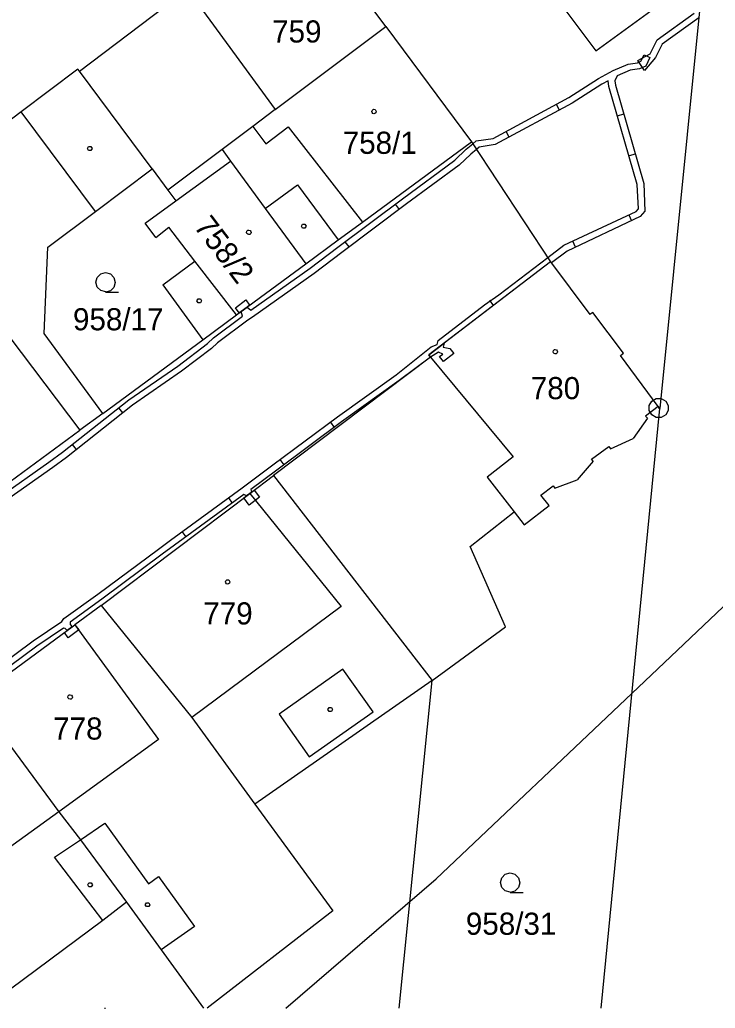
# Model space of a CAD drawing. Extents: x -777309 to -774195, y -1144706 to -1143600.
# Drawn here: x -775185.7 to -775132.3, y -1144700 to -1144624.1 of the extents above; entities that cross this region are included whole.
import ezdxf

# ---------------------------------------------------------------- set-up
doc = ezdxf.new("R2010")
doc.units = 0
for name, color, linetype in [('1', 7, 'Continuous'), ('11', 7, 'Continuous'), ('12', 7, 'Continuous'), ('13', 7, 'Continuous'), ('2', 7, 'Continuous'), ('3', 7, 'Continuous'), ('4', 7, 'Continuous'), ('5', 7, 'Continuous'), ('8', 7, 'Continuous')]:
    doc.layers.add(name, color=color, linetype=linetype)

msp = doc.modelspace()

# ---------------------------------------------------------------- linework, layer by layer
at = {"layer": '1'}
for p, q in [((-775157.61, -1144624.62), (-775164.34, -1144615.55)), ((-775141.48, -1144626.47), (-775133.23, -1144620.45)), ((-775133.23, -1144620.45), (-775136.58, -1144653.95)), ((-775181.15, -1144628.05), (-775172.84, -1144621.74)), ((-775144.69, -1144622.2), (-775141.48, -1144626.47)), ((-775166.11, -1144630.99), (-775157.61, -1144624.62)), ((-775157.61, -1144624.62), (-775151.04, -1144633.47)), ((-775181.27, -1144627.89), (-775185.64, -1144631.15)), ((-775181.15, -1144628.05), (-775181.27, -1144627.89)), ((-775175.57, -1144635.55), (-775181.15, -1144628.05)), ((-775185.64, -1144631.15), (-775189.64, -1144634.21)), ((-775166.11, -1144630.99), (-775167.84, -1144632.28)), ((-775167.84, -1144632.28), (-775170.2, -1144634.05)), ((-775159.42, -1144639.64), (-775151.04, -1144633.47)), ((-775151.04, -1144633.47), (-775144.97, -1144642.68)), ((-775170.2, -1144634.05), (-775174.36, -1144637.17)), ((-775170.2, -1144634.05), (-775169.55, -1144634.94)), ((-775169.55, -1144634.94), (-775166.89, -1144638.59)), ((-775179.93, -1144638.81), (-775175.57, -1144635.55)), ((-775175.57, -1144635.55), (-775174.36, -1144637.17)), ((-775174.36, -1144637.17), (-775173.74, -1144638)), ((-775176.1, -1144639.72), (-775173.74, -1144638)), ((-775183.59, -1144641.55), (-775179.93, -1144638.81)), ((-775166.89, -1144638.59), (-775163.77, -1144642.84)), ((-775175.28, -1144640.81), (-775176.1, -1144639.72)), ((-775161.27, -1144641), (-775159.42, -1144639.64)), ((-775175.28, -1144640.81), (-775174.29, -1144640.02)), ((-775172.28, -1144642.63), (-775174.29, -1144640.02)), ((-775163.77, -1144642.84), (-775161.27, -1144641)), ((-775183.87, -1144648.18), (-775183.59, -1144641.55)), ((-775174.76, -1144644.46), (-775172.28, -1144642.63)), ((-775169.09, -1144646.76), (-775163.77, -1144642.84)), ((-775144.97, -1144642.68), (-775154.31, -1144649.83)), ((-775144.97, -1144642.68), (-775141.94, -1144646.72)), ((-775174.76, -1144644.46), (-775171.67, -1144648.66)), ((-775141.72, -1144646.56), (-775141.94, -1144646.72)), ((-775139.37, -1144649.7), (-775141.72, -1144646.56)), ((-775187.72, -1144646.9), (-775181.13, -1144655.62)), ((-775171.67, -1144648.66), (-775169.09, -1144646.76)), ((-775179.36, -1144654.32), (-775183.87, -1144648.18)), ((-775179.36, -1144654.32), (-775171.67, -1144648.66)), ((-775154.19, -1144649.99), (-775166.24, -1144659.08)), ((-775154.31, -1144649.83), (-775154.19, -1144649.99)), ((-775139.6, -1144649.87), (-775139.37, -1144649.7)), ((-775136.71, -1144653.79), (-775139.6, -1144649.87)), ((-775141.074, -1144700), (-775136.58, -1144653.95)), ((-775136.71, -1144653.79), (-775137.66, -1144654.53)), ((-775136.71, -1144653.79), (-775136.58, -1144653.95)), ((-775179.36, -1144654.32), (-775181.13, -1144655.62)), ((-775137.53, -1144654.68), (-775138.62, -1144656.25)), ((-775137.66, -1144654.53), (-775137.53, -1144654.68)), ((-775190.02, -1144662.15), (-775181.13, -1144655.62)), ((-775140.36, -1144657.04), (-775138.62, -1144656.25)), ((-775141.81, -1144657.83), (-775140.48, -1144656.87)), ((-775140.48, -1144656.87), (-775140.36, -1144657.04)), ((-775141.69, -1144658), (-775142.92, -1144659.43)), ((-775141.69, -1144658), (-775141.81, -1144657.83)), ((-775168.07, -1144660.46), (-775166.24, -1144659.08)), ((-775166.24, -1144659.08), (-775154.07, -1144674.84)), ((-775144.63, -1144660.05), (-775142.92, -1144659.43)), ((-775145.7, -1144660.59), (-775144.76, -1144659.88)), ((-775144.76, -1144659.88), (-775144.63, -1144660.05)), ((-775179.48, -1144669.07), (-775168.07, -1144660.46)), ((-775145.08, -1144661.39), (-775145.7, -1144660.59)), ((-775146.99, -1144662.87), (-775145.08, -1144661.39)), ((-775151.13, -1144664.54), (-775147.76, -1144661.89)), ((-775147.76, -1144661.89), (-775146.99, -1144662.87)), ((-775148.42, -1144670.72), (-775151.13, -1144664.54)), ((-775179.48, -1144669.07), (-775181.5, -1144670.55)), ((-775179.48, -1144669.07), (-775172.51, -1144677.68)), ((-775189.17, -1144676.2), (-775181.5, -1144670.55)), ((-775154.07, -1144674.84), (-775148.42, -1144670.72)), ((-775154.07, -1144674.84), (-775167.67, -1144684.33)), ((-775156.607, -1144700), (-775154.07, -1144674.84)), ((-775189.17, -1144676.2), (-775182.75, -1144684.92)), ((-775172.51, -1144677.68), (-775167.67, -1144684.33)), ((-775167.67, -1144684.33), (-775161.68, -1144692.51)), ((-775182.75, -1144684.92), (-775181.07, -1144687.07)), ((-775181.07, -1144687.07), (-775177.55, -1144691.86)), ((-775177.55, -1144691.86), (-775179.35, -1144693.26)), ((-775177.55, -1144691.86), (-775174.87, -1144695.51)), ((-775161.68, -1144692.51), (-775171.339, -1144700)), ((-775179.35, -1144693.26), (-775187.68, -1144699.45)), ((-775174.87, -1144695.51), (-775171.621, -1144700))]:
    msp.add_line(p, q, dxfattribs=at)
at = {"layer": '11'}
msp.add_lwpolyline([(-775165.303, -1144700), (-775153.75, -1144690.06), (-775138.71, -1144675.82), (-775130.21, -1144667.77)], dxfattribs=at)
at = {"layer": '12'}
for p, q in [((-775157.61, -1144624.62), (-775164.34, -1144615.55)), ((-775172.84, -1144621.74), (-775166.11, -1144630.99)), ((-775166.11, -1144630.99), (-775157.61, -1144624.62)), ((-775166.11, -1144630.99), (-775157.61, -1144624.62)), ((-775157.61, -1144624.62), (-775151.04, -1144633.47)), ((-775166.11, -1144630.99), (-775167.84, -1144632.28)), ((-775167.84, -1144632.28), (-775166.84, -1144633.61)), ((-775166.84, -1144633.61), (-775165.11, -1144632.32)), ((-775165.11, -1144632.32), (-775159.42, -1144639.64)), ((-775159.42, -1144639.64), (-775151.04, -1144633.47)), ((-775173.74, -1144638), (-775169.55, -1144634.94)), ((-775169.55, -1144634.94), (-775166.89, -1144638.59)), ((-775176.1, -1144639.72), (-775173.74, -1144638)), ((-775166.89, -1144638.59), (-775163.77, -1144642.84)), ((-775175.28, -1144640.81), (-775176.1, -1144639.72)), ((-775175.28, -1144640.81), (-775174.29, -1144640.02)), ((-775172.28, -1144642.63), (-775174.29, -1144640.02)), ((-775169.09, -1144646.76), (-775172.28, -1144642.63)), ((-775169.09, -1144646.76), (-775163.77, -1144642.84)), ((-775144.97, -1144642.68), (-775154.31, -1144649.83)), ((-775144.97, -1144642.68), (-775141.94, -1144646.72)), ((-775141.72, -1144646.56), (-775141.94, -1144646.72)), ((-775139.37, -1144649.7), (-775141.72, -1144646.56)), ((-775154.31, -1144649.83), (-775154.19, -1144649.99)), ((-775154.19, -1144649.99), (-775147.85, -1144657.66)), ((-775139.6, -1144649.87), (-775139.37, -1144649.7)), ((-775136.71, -1144653.79), (-775139.6, -1144649.87)), ((-775136.71, -1144653.79), (-775137.66, -1144654.53)), ((-775137.53, -1144654.68), (-775138.62, -1144656.25)), ((-775137.66, -1144654.53), (-775137.53, -1144654.68)), ((-775140.36, -1144657.04), (-775138.62, -1144656.25)), ((-775141.81, -1144657.83), (-775140.48, -1144656.87)), ((-775140.48, -1144656.87), (-775140.36, -1144657.04)), ((-775147.85, -1144657.66), (-775149.84, -1144659.21)), ((-775141.69, -1144658), (-775142.92, -1144659.43)), ((-775141.69, -1144658), (-775141.81, -1144657.83)), ((-775149.84, -1144659.21), (-775147.76, -1144661.89)), ((-775144.63, -1144660.05), (-775142.92, -1144659.43)), ((-775145.7, -1144660.59), (-775144.76, -1144659.88)), ((-775144.76, -1144659.88), (-775144.63, -1144660.05)), ((-775179.48, -1144669.07), (-775168.07, -1144660.46)), ((-775168.07, -1144660.46), (-775161.04, -1144669.16)), ((-775145.08, -1144661.39), (-775145.7, -1144660.59)), ((-775146.99, -1144662.87), (-775145.08, -1144661.39)), ((-775147.76, -1144661.89), (-775146.99, -1144662.87)), ((-775179.48, -1144669.07), (-775172.51, -1144677.68)), ((-775161.04, -1144669.16), (-775172.51, -1144677.68)), ((-775189.17, -1144676.2), (-775181.5, -1144670.55)), ((-775181.5, -1144670.55), (-775175.07, -1144679.37)), ((-775189.17, -1144676.2), (-775182.75, -1144684.92)), ((-775189.17, -1144676.2), (-775182.75, -1144684.92)), ((-775175.07, -1144679.37), (-775182.75, -1144684.92)), ((-775182.75, -1144684.92), (-775190.37, -1144690.43))]:
    msp.add_line(p, q, dxfattribs=at)
at = {"layer": '13'}
for p, q in [((-775136.78, -1144625.63), (-775133.93, -1144623.59)), ((-775133.58, -1144623.95), (-775136.38, -1144625.97)), ((-775137.32, -1144626.7), (-775136.78, -1144625.63)), ((-775136.38, -1144625.97), (-775136.9, -1144626.98)), ((-775138.27, -1144627.21), (-775137.32, -1144626.7)), ((-775138.02, -1144627.27), (-775137.78, -1144626.78)), ((-775137.78, -1144626.78), (-775137.33, -1144626.99)), ((-775140.15, -1144628), (-775139, -1144627.49)), ((-775139, -1144627.49), (-775138.28, -1144627.39)), ((-775138.28, -1144627.39), (-775138.02, -1144627.27)), ((-775137.75, -1144628), (-775138.27, -1144627.21)), ((-775137.64, -1144627.65), (-775138.14, -1144627.87)), ((-775136.9, -1144626.98), (-775137.75, -1144628)), ((-775137.33, -1144626.99), (-775137.64, -1144627.65)), ((-775141.29, -1144628.6), (-775140.15, -1144628)), ((-775139.85, -1144628.41), (-775140.03, -1144628.78)), ((-775138.86, -1144627.97), (-775139.85, -1144628.41)), ((-775138.14, -1144627.87), (-775138.86, -1144627.97)), ((-775143.57, -1144630.05), (-775141.29, -1144628.6)), ((-775141.03, -1144629.04), (-775143.31, -1144630.49)), ((-775140.54, -1144628.77), (-775141.03, -1144629.04)), ((-775140.48, -1144629.22), (-775140.54, -1144628.77)), ((-775140.03, -1144628.78), (-775139.98, -1144629.12)), ((-775139.98, -1144629.12), (-775137.8, -1144636.67)), ((-775138.3, -1144636.75), (-775140.48, -1144629.22)), ((-775149.38, -1144633.2), (-775143.57, -1144630.05)), ((-775143.31, -1144630.49), (-775149.22, -1144633.68)), ((-775144.545, -1144630.579), (-775144.307, -1144631.018)), ((-775139.829, -1144631.467), (-775139.349, -1144631.328)), ((-775148.15, -1144633.102), (-775148.388, -1144632.663)), ((-775151.44, -1144634.04), (-775150.94, -1144633.62)), ((-775150.94, -1144633.62), (-775150.67, -1144633.39)), ((-775150.67, -1144633.39), (-775149.38, -1144633.2)), ((-775149.22, -1144633.68), (-775150.45, -1144633.87)), ((-775152.31, -1144634.87), (-775151.44, -1144634.04)), ((-775151.1, -1144634.42), (-775151.99, -1144635.25)), ((-775150.66, -1144634.05), (-775151.1, -1144634.42)), ((-775150.45, -1144633.87), (-775150.66, -1144634.05)), ((-775138.454, -1144634.404), (-775138.935, -1144634.543)), ((-775156.34, -1144637.84), (-775152.31, -1144634.87)), ((-775151.99, -1144635.25), (-775156.04, -1144638.24)), ((-775138.22, -1144638.61), (-775138.3, -1144636.75)), ((-775137.8, -1144636.67), (-775137.72, -1144638.79)), ((-775161.31, -1144641.56), (-775156.34, -1144637.84)), ((-775156.04, -1144638.24), (-775161.01, -1144641.96)), ((-775156.907, -1144638.264), (-775156.607, -1144638.664)), ((-775143.94, -1144641.41), (-775138.39, -1144638.81)), ((-775138.39, -1144638.81), (-775138.22, -1144638.61)), ((-775137.72, -1144638.79), (-775138.07, -1144639.21)), ((-775138.07, -1144639.21), (-775143.68, -1144641.85)), ((-775138.959, -1144639.077), (-775138.747, -1144639.53)), ((-775160.443, -1144641.536), (-775160.743, -1144641.135)), ((-775143.047, -1144641.552), (-775143.259, -1144641.099)), ((-775163.43, -1144643.18), (-775161.31, -1144641.56)), ((-775161.01, -1144641.96), (-775163.13, -1144643.58)), ((-775145.18, -1144642.36), (-775143.94, -1144641.41)), ((-775143.68, -1144641.85), (-775144.9, -1144642.77)), ((-775144.97, -1144642.68), (-775153.14, -1144648.93)), ((-775148.95, -1144645.22), (-775145.18, -1144642.36)), ((-775144.9, -1144642.77), (-775144.97, -1144642.68)), ((-775167.98, -1144646.4), (-775163.43, -1144643.18)), ((-775163.13, -1144643.58), (-775167.85, -1144646.92)), ((-775150.03, -1144645.98), (-775148.95, -1144645.22)), ((-775149.338, -1144646.022), (-775149.642, -1144645.625)), ((-775168.72, -1144646.49), (-775168.27, -1144646.16)), ((-775168.64, -1144646.86), (-775168.72, -1144646.49)), ((-775168.27, -1144646.16), (-775167.98, -1144646.4)), ((-775153.6, -1144648.72), (-775150.03, -1144645.98)), ((-775170.86, -1144648.52), (-775168.64, -1144646.86)), ((-775168.22, -1144647.17), (-775170.54, -1144648.9)), ((-775167.85, -1144646.92), (-775168.22, -1144647.17)), ((-775171.32, -1144648.95), (-775170.86, -1144648.52)), ((-775170.54, -1144648.9), (-775171, -1144649.33)), ((-775153.68, -1144649.04), (-775153.6, -1144648.72)), ((-775173.61, -1144650.69), (-775171.32, -1144648.95)), ((-775171, -1144649.33), (-775173.31, -1144651.09)), ((-775156.82, -1144651.35), (-775154.13, -1144649.21)), ((-775154.13, -1144649.21), (-775153.68, -1144649.04)), ((-775154.19, -1144649.99), (-775156.59, -1144651.8)), ((-775177.37, -1144653.28), (-775173.61, -1144650.69)), ((-775173.31, -1144651.09), (-775177.07, -1144653.68)), ((-775161.32, -1144654.58), (-775156.82, -1144651.35)), ((-775156.59, -1144651.8), (-775161.02, -1144654.98)), ((-775182.46, -1144657.31), (-775177.37, -1144653.28)), ((-775177.07, -1144653.68), (-775182.16, -1144657.71)), ((-775178.148, -1144653.896), (-775177.837, -1144654.288)), ((-775166.29, -1144658.28), (-775161.32, -1144654.58)), ((-775161.02, -1144654.98), (-775165.99, -1144658.68)), ((-775161.878, -1144654.996), (-775161.58, -1144655.397)), ((-775181.382, -1144657.094), (-775181.692, -1144656.702)), ((-775183.5, -1144658.07), (-775182.46, -1144657.31)), ((-775182.16, -1144657.71), (-775183.2, -1144658.47)), ((-775165.432, -1144658.264), (-775165.73, -1144657.863)), ((-775187.29, -1144660.74), (-775183.5, -1144658.07)), ((-775183.2, -1144658.47), (-775187.01, -1144661.16)), ((-775168.45, -1144659.89), (-775166.29, -1144658.28)), ((-775165.99, -1144658.68), (-775167.99, -1144660.17)), ((-775174.16, -1144664.05), (-775168.65, -1144660.03)), ((-775168.65, -1144660.03), (-775168.45, -1144659.89)), ((-775167.99, -1144660.17), (-775167.93, -1144660.36)), ((-775168.53, -1144660.55), (-775173.86, -1144664.45)), ((-775169.717, -1144660.808), (-775169.422, -1144661.212)), ((-775168.33, -1144660.66), (-775168.53, -1144660.55)), ((-775175.09, -1144664.74), (-775174.16, -1144664.05)), ((-775172.969, -1144663.798), (-775173.264, -1144663.394)), ((-775179.74, -1144668.19), (-775175.09, -1144664.74)), ((-775173.86, -1144664.45), (-775174.79, -1144665.14)), ((-775174.79, -1144665.14), (-775179.44, -1144668.59)), ((-775182.35, -1144670.08), (-775179.74, -1144668.19)), ((-775179.44, -1144668.59), (-775181.87, -1144670.34)), ((-775182.51, -1144670.3), (-775182.35, -1144670.08)), ((-775184.72, -1144671.79), (-775182.51, -1144670.3)), ((-775182.39, -1144670.82), (-775184.44, -1144672.19)), ((-775182.26, -1144670.84), (-775182.39, -1144670.82)), ((-775182.11, -1144671), (-775182.26, -1144670.84)), ((-775181.71, -1144670.7), (-775182.11, -1144671)), ((-775181.87, -1144670.34), (-775181.88, -1144670.52)), ((-775181.88, -1144670.52), (-775181.71, -1144670.7)), ((-775190.56, -1144676.11), (-775184.72, -1144671.79)), ((-775184.44, -1144672.19), (-775190.26, -1144676.51))]:
    msp.add_line(p, q, dxfattribs=at)
for points in [[(-775168.38, -1144645.61), (-775168.08, -1144646.02), (-775168.27, -1144646.16), (-775168.72, -1144646.49), (-775168.89, -1144646.61), (-775169.18, -1144646.21)], [(-775154.19, -1144649.99), (-775154.31, -1144649.83), (-775153.14, -1144648.93), (-775153.21, -1144649.23), (-775152.7, -1144649.33), (-775152.39, -1144649.73), (-775153.19, -1144650.34), (-775153.49, -1144649.94), (-775153.25, -1144649.76), (-775153.58, -1144649.61)], [(-775167.32, -1144660.76), (-775168.12, -1144661.36), (-775168.53, -1144660.81), (-775168.33, -1144660.66), (-775168.07, -1144660.46), (-775167.93, -1144660.36), (-775167.74, -1144660.21)], [(-775182.01, -1144671.55), (-775182.31, -1144671.15), (-775182.11, -1144671), (-775181.71, -1144670.7), (-775181.5, -1144670.55), (-775181.21, -1144670.95)]]:
    msp.add_lwpolyline(points, close=True, dxfattribs=at)
for points in [[(-775153.14, -1144648.93), (-775154.31, -1144649.83), (-775154.19, -1144649.99)], [(-775167.93, -1144660.36), (-775168.07, -1144660.46), (-775168.33, -1144660.66)]]:
    msp.add_lwpolyline(points, dxfattribs=at)
at = {"layer": '3'}
for points in [[(-775179.14, -1144644.99), (-775179.52, -1144644.89), (-775179.79, -1144644.62), (-775179.89, -1144644.25), (-775179.79, -1144643.88), (-775179.52, -1144643.61), (-775179.15, -1144643.51), (-775178.78, -1144643.61), (-775178.51, -1144643.88), (-775178.41, -1144644.26), (-775178.51, -1144644.64), (-775178.78, -1144644.91), (-775179.16, -1144645.01), (-775178.16, -1144645.01)], [(-775148.06, -1144691.09), (-775148.44, -1144690.99), (-775148.71, -1144690.72), (-775148.81, -1144690.35), (-775148.71, -1144689.98), (-775148.44, -1144689.71), (-775148.07, -1144689.61), (-775147.7, -1144689.71), (-775147.43, -1144689.98), (-775147.33, -1144690.36), (-775147.43, -1144690.74), (-775147.7, -1144691.01), (-775148.08, -1144691.11), (-775147.08, -1144691.11)], [(-775179.227, -1144700), (-775179.19, -1144699.99), (-775179.153, -1144700)]]:
    msp.add_lwpolyline(points, dxfattribs=at)
at = {"layer": '4'}
for p, q in [((-775172.84, -1144621.74), (-775166.11, -1144630.99)), ((-775179.93, -1144638.81), (-775185.64, -1144631.15)), ((-775167.84, -1144632.28), (-775166.84, -1144633.61)), ((-775166.84, -1144633.61), (-775165.11, -1144632.32)), ((-775165.11, -1144632.32), (-775159.42, -1144639.64)), ((-775173.74, -1144638), (-775169.55, -1144634.94)), ((-775166.89, -1144638.59), (-775164.4, -1144636.76)), ((-775164.4, -1144636.76), (-775161.27, -1144641)), ((-775169.09, -1144646.76), (-775172.28, -1144642.63)), ((-775154.19, -1144649.99), (-775147.85, -1144657.66)), ((-775147.85, -1144657.66), (-775149.84, -1144659.21)), ((-775149.84, -1144659.21), (-775147.76, -1144661.89)), ((-775168.07, -1144660.46), (-775161.04, -1144669.16)), ((-775161.04, -1144669.16), (-775172.51, -1144677.68)), ((-775181.5, -1144670.55), (-775175.07, -1144679.37)), ((-775160.92, -1144673.96), (-775165.82, -1144677.41)), ((-775158.59, -1144677.24), (-775160.92, -1144673.96)), ((-775165.82, -1144677.41), (-775163.51, -1144680.69)), ((-775163.51, -1144680.69), (-775158.59, -1144677.24)), ((-775175.07, -1144679.37), (-775182.75, -1144684.92)), ((-775182.75, -1144684.92), (-775190.37, -1144690.43)), ((-775181.07, -1144687.07), (-775179.2, -1144685.78)), ((-775179.2, -1144685.78), (-775175.85, -1144690.44)), ((-775183.08, -1144688.41), (-775181.07, -1144687.07)), ((-775179.35, -1144693.26), (-775183.08, -1144688.41)), ((-775175.85, -1144690.44), (-775175.08, -1144689.89)), ((-775175.08, -1144689.89), (-775172.33, -1144693.73)), ((-775172.33, -1144693.73), (-775174.87, -1144695.51))]:
    msp.add_line(p, q, dxfattribs=at)
at = {"layer": '5'}
for points in [[(-775158.53, -1144630.97), (-775158.43, -1144630.99), (-775158.38, -1144631.08), (-775158.36, -1144631.14), (-775158.38, -1144631.23), (-775158.46, -1144631.3), (-775158.53, -1144631.31), (-775158.62, -1144631.28), (-775158.68, -1144631.22), (-775158.7, -1144631.14), (-775158.68, -1144631.05), (-775158.6, -1144630.98)], [(-775180.27, -1144633.82), (-775180.18, -1144633.97), (-775180.27, -1144634.12), (-775180.45, -1144634.12), (-775180.54, -1144633.97), (-775180.45, -1144633.82)], [(-775163.83, -1144639.79), (-775163.74, -1144639.94), (-775163.83, -1144640.09), (-775164.01, -1144640.09), (-775164.1, -1144639.94), (-775164.01, -1144639.79)], [(-775168.14, -1144640.25), (-775168.04, -1144640.27), (-775167.99, -1144640.36), (-775167.97, -1144640.42), (-775167.99, -1144640.51), (-775168.07, -1144640.58), (-775168.14, -1144640.59), (-775168.23, -1144640.56), (-775168.29, -1144640.5), (-775168.31, -1144640.42), (-775168.29, -1144640.33), (-775168.21, -1144640.26)], [(-775171.86, -1144645.52), (-775171.77, -1144645.67), (-775171.86, -1144645.82), (-775172.04, -1144645.82), (-775172.13, -1144645.67), (-775172.04, -1144645.52)], [(-775144.6, -1144649.41), (-775144.5, -1144649.43), (-775144.45, -1144649.52), (-775144.43, -1144649.58), (-775144.45, -1144649.67), (-775144.53, -1144649.74), (-775144.6, -1144649.75), (-775144.69, -1144649.72), (-775144.75, -1144649.66), (-775144.77, -1144649.58), (-775144.75, -1144649.49), (-775144.67, -1144649.42)], [(-775169.77, -1144667.09), (-775169.67, -1144667.11), (-775169.62, -1144667.2), (-775169.6, -1144667.26), (-775169.62, -1144667.35), (-775169.7, -1144667.42), (-775169.77, -1144667.43), (-775169.86, -1144667.4), (-775169.92, -1144667.34), (-775169.94, -1144667.26), (-775169.92, -1144667.17), (-775169.84, -1144667.1)], [(-775181.87, -1144675.93), (-775181.77, -1144675.95), (-775181.72, -1144676.04), (-775181.7, -1144676.1), (-775181.72, -1144676.19), (-775181.8, -1144676.26), (-775181.87, -1144676.27), (-775181.96, -1144676.24), (-775182.02, -1144676.18), (-775182.04, -1144676.1), (-775182.02, -1144676.01), (-775181.94, -1144675.94)], [(-775161.8, -1144676.91), (-775161.71, -1144677.06), (-775161.8, -1144677.21), (-775161.98, -1144677.21), (-775162.07, -1144677.06), (-775161.98, -1144676.91)], [(-775180.25, -1144690.37), (-775180.16, -1144690.52), (-775180.25, -1144690.67), (-775180.43, -1144690.67), (-775180.52, -1144690.52), (-775180.43, -1144690.37)], [(-775175.83, -1144691.9), (-775175.74, -1144692.05), (-775175.83, -1144692.2), (-775176.01, -1144692.2), (-775176.1, -1144692.05), (-775176.01, -1144691.9)]]:
    msp.add_lwpolyline(points, close=True, dxfattribs=at)
at = {"layer": '8'}
msp.add_line((-775136.7, -1144653.9), (-775136.6, -1144653.9), dxfattribs=at)
msp.add_lwpolyline([(-775136.46, -1144653.18), (-775136.12, -1144653.37), (-775135.93, -1144653.71), (-775135.93, -1144654.1), (-775136.12, -1144654.44), (-775136.46, -1144654.63), (-775136.85, -1144654.63), (-775137.19, -1144654.44), (-775137.38, -1144654.1), (-775137.38, -1144653.71), (-775137.19, -1144653.37), (-775136.85, -1144653.18)], close=True, dxfattribs=at)

# ---------------------------------------------------------------- texts
at = {"layer": '2'}
for s, p in [('759', (-775166.353, -1144625.84)), ('758/1', (-775160.933, -1144634.39)), ('958/17', (-775181.653, -1144647.94)), ('780', (-775146.483, -1144653.23)), ('779', (-775171.643, -1144670.53)), ('778', (-775183.173, -1144679.37)), ('958/31', (-775151.473, -1144694.36))]:
    msp.add_text(s, height=1.7, dxfattribs=at).set_placement(p)
msp.add_text('758/2', height=1.7, rotation=307.21997, dxfattribs=at).set_placement((-775172.426, -1144639.979))

doc.saveas('drawing.dxf')
